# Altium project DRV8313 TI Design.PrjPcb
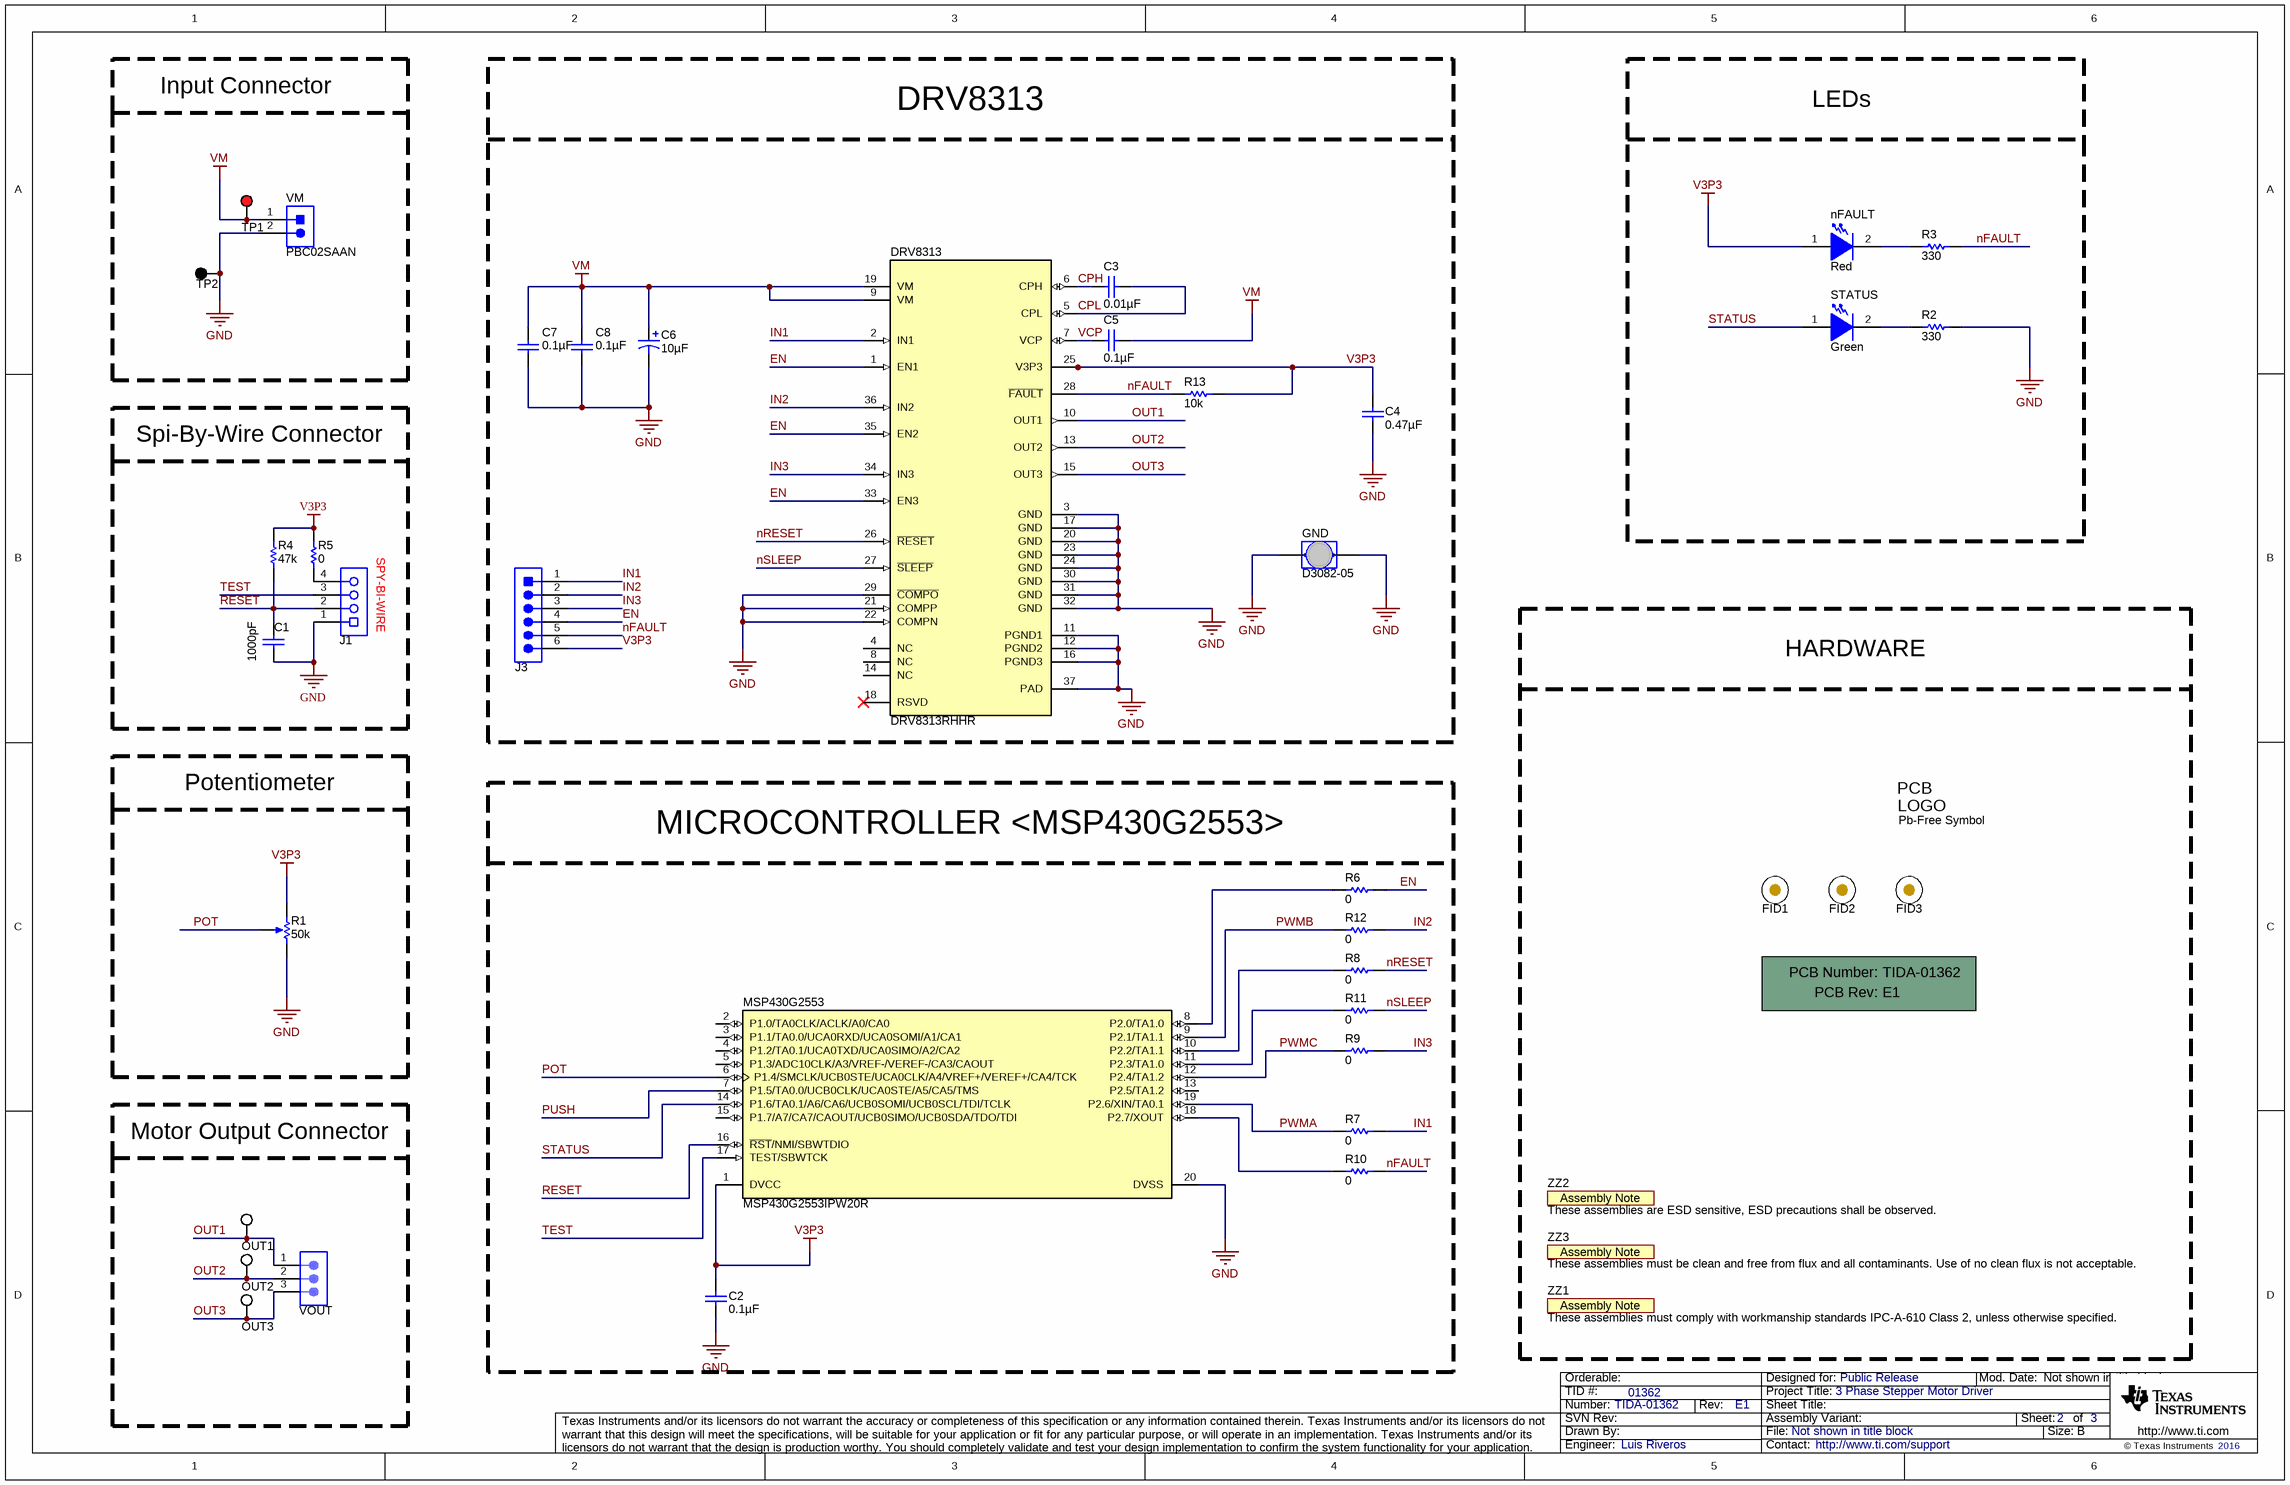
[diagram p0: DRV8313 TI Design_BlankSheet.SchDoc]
CopyrightYear: 2016; PCB_Layout: Luis Riveros; PCB_Rev: E1; PRJ_Customer: Public Release; PRJ_Engineer: Luis Riveros; PRJ_Number: TIDA-01362; PRJ_Title: 3 Phase Stepper Motor Driver; SCH_Rev: E1; TechSupport: http://www.ti.com/support; TID: 01362
1 sheet, 43 parts. Net scope: global (net labels, ports and power ports of the same name join across sheets).
Board file: DRV8313 TI Design_PCB.PcbDoc

## Sheet DRV8313 TI Design_BlankSheet.SchDoc
size 431 x 279 mm; Date: Not shown in title block; ApprovedBy: Not shown in title block; CheckedBy: Not shown in title block; Author: Not shown in title block; CompanyName: Not shown in title block; Engineer: Not shown in title block; Organization: Not shown in title block; Address1: Not shown in title block; Address2: Not shown in title block; Address3: Not shown in title block; Address4: Not shown in title block; DocumentNumber: 1; Revision: Use project parameter SCH_Rev; SheetNumber: 2; SheetTotal: 3; PageSetup: Record=PageOptions¦CenterHorizontal=True¦CenterVertical=True¦PrintScale=1.00¦XCorrection=1.00¦YCorrection=1.00¦PrintKind=0¦BorderSize=5000000¦LeftOffset=0¦BottomOffset=0¦Orientation=2¦PaperLength=1000¦PaperWidth=1000¦Scale=100¦PaperSource=15¦PrintQuality=600¦MediaType=1¦DitherType=10¦PaperKind=Letter¦PrintScaleMode=1

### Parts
!PCB  Printed Circuit Board  (value not drawn)  (mechanical)
C1  ValueDisplayed: 1000pF  [0603L]  (hidden comment: GRM188R71C102KA01D)
C2  ValueDisplayed: 0.1µF  [0603L]  (hidden comment: C0603C104K8RACTU)
C3  0.01µF  [0603]
C4  ValueDisplayed: 0.47µF  [0603]  (hidden comment: GCM188R71C474KA55D)
C5  ValueDisplayed: 0.1µF  [0805_HV]  (hidden comment: C2012X5R2A104K125AA)
C6  ValueDisplayed: 10µF  [SM_RADIAL_D8]  (hidden comment: EEE-FK1K100XP)
C7  ValueDisplayed: 0.1µF  [0805_HV]  (hidden comment: C2012X5R2A104K125AA)
C8  ValueDisplayed: 0.1µF  [0805_HV]  (hidden comment: C2012X5R2A104K125AA)
DRV8313  DRV8313RHHR  [RHH0036C]
FID1  Fiducial  [Fiducial10-20]  (value not drawn)
FID2  Fiducial  [Fiducial10-20]  (value not drawn)
FID3  Fiducial  [Fiducial10-20]  (value not drawn)
GND  D3082-05  [Harwin_D3082-05]
J1  851-43-004-20-001000  [CONN_851-43-004-20-001000]  (value not drawn)
J3  PEC06SAAN  [Sullins_PEC06SAAN]  (value not drawn)
Logo2  Pb-Free Symbol  [Pb-Free_Overlay_Small]  (no BOM)
MSP430G2553  MSP430G2553IPW20R  [PW0020A_N]
nFAULT  value Red  [LED_LTST-C170_Red]  (hidden comment: LTST-C170KRKT)
OUT1  5002  [Keystone5002]  (value not drawn)
OUT2  5002  [Keystone5002]  (value not drawn)
OUT3  5002  [Keystone5002]  (value not drawn)
R1  value 50k  [Bourns_3352T]  (hidden comment: 3352T-1-503LF)
R2  ValueDisplayed: 330  [0603]  (hidden comment: CRCW0603330RJNEA)
R3  ValueDisplayed: 330  [0603]  (hidden comment: CRCW0603330RJNEA)
R4  value 47k  [0603L]  (hidden comment: CRCW060347K0JNEA)
R5  value 0  [0603L]  (hidden comment: CRCW06030000Z0EA)
R6  value 0  [0603L]  (hidden comment: CRCW06030000Z0EA)
R7  ValueDisplayed: 0  [0805_HV]  (hidden comment: ERJ-6GEY0R00V)
R8  value 0  [0603L]  (hidden comment: CRCW06030000Z0EA)
R9  ValueDisplayed: 0  [0805_HV]  (hidden comment: ERJ-6GEY0R00V)
R10  value 0  [0603L]  (hidden comment: CRCW06030000Z0EA)
R11  value 0  [0603L]  (hidden comment: CRCW06030000Z0EA)
R12  ValueDisplayed: 0  [0805_HV]  (hidden comment: ERJ-6GEY0R00V)
R13  ValueDisplayed: 10k  [0805_HV]  (hidden comment: CRCW080510K0JNEA)
STATUS  value Green  [LTST-C170KGKT_Green]  (hidden comment: LTST-C170KGKT)
TP1  5000  [Keystone5000]  (value not drawn)
TP2  5001  [Keystone5001]  (value not drawn)
VM  PBC02SAAN  [Sullins_PBC02SAAN]
VOUT  PBC03SAAN  [PBC03SAAN]  (value not drawn)
ZZ1  These assemblies must comply with workmanship standards IPC-A-610 Class 2, unless otherwise specified.  [AssemblyNote]  (no BOM)
ZZ2  These assemblies are ESD sensitive, ESD precautions shall be observed.  [AssemblyNote]  (no BOM)
ZZ3  These assemblies must be clean and free from flux and all contaminants. Use of no clean flux is not acceptable.  [AssemblyNote]  (no BOM)

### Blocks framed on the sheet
DRV8313: C3-C8 DRV8313 GND J3 R13
SPY-BI-WIRE: C1 J1 R4 R5
HARDWARE: !PCB FID1-FID3 Logo2 ZZ1-ZZ3

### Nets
GND: C1.2 C2.2 C4.2 C6.2(-) C7.1 C8.2 DRV8313.3(GND) DRV8313.11(PGND1) DRV8313.12(PGND2) DRV8313.16(PGND3) DRV8313.17(GND) DRV8313.20(GND) DRV8313.21(COMPP) DRV8313.22(COMPN) DRV8313.23(GND) DRV8313.24(GND) DRV8313.29(~{COMPO}) DRV8313.30(GND) DRV8313.31(GND) DRV8313.32(GND) DRV8313.37(PAD) GND.1 GND.2 J1.1 MSP430G2553.20(DVSS) R1.3(CW) R2.2 TP2.1 VM.2
V3P3: C2.1 C4.1 DRV8313.25(V3P3) J3.6 MSP430G2553.1(DVCC) nFAULT.1(A) R1.1(CCW) R4.2 R5.2 R13.2
VM: C5.2 C6.1(+) C7.2 C8.1 DRV8313.9(VM) DRV8313.19(VM) TP1.1 VM.1
CPH: C3.2 DRV8313.6(CPH)
CPL: C3.1 DRV8313.5(CPL)
EN: DRV8313.1(EN1) DRV8313.33(EN3) DRV8313.35(EN2) J3.4 R6.1
IN1: DRV8313.2(IN1) J3.1 R7.2
IN2: DRV8313.36(IN2) J3.2 R12.2
IN3: DRV8313.34(IN3) J3.3 R9.2
nFAULT: DRV8313.28(~{FAULT}) J3.5 R3.2 R10.1 R13.1
nRESET: DRV8313.26(~{RESET}) R8.1
nSLEEP: DRV8313.27(~{SLEEP}) R11.1
OUT1: DRV8313.10(OUT1) OUT1.1 VOUT.1
OUT2: DRV8313.13(OUT2) OUT2.1 VOUT.2
OUT3: DRV8313.15(OUT3) OUT3.1 VOUT.3
POT: MSP430G2553.6(P1.4/SMCLK/UCB0STE/UCA0CLK/A4/VREF+/VEREF+/CA4/TCK) R1.2(WIPER)
PUSH: MSP430G2553.7(P1.5/TA0.0/UCB0CLK/UCA0STE/A5/CA5/TMS)
PWMA: MSP430G2553.19(P2.6/XIN/TA0.1) R7.1
PWMB: MSP430G2553.9(P2.1/TA1.1) R12.1
PWMC: MSP430G2553.12(P2.4/TA1.2) R9.1
RESET: C1.1 J1.2 MSP430G2553.16(~{RST}/NMI/SBWTDIO) R4.1
STATUS: MSP430G2553.14(P1.6/TA0.1/A6/CA6/UCB0SOMI/UCB0SCL/TDI/TCLK) STATUS.1(A)
TEST: J1.3 MSP430G2553.17(TEST/SBWTCK)
VCP: C5.1 DRV8313.7(VCP)
NetJ1_4: J1.4 R5.1
NetMSP430G2553_8: MSP430G2553.8(P2.0/TA1.0) R6.2
NetMSP430G2553_10: MSP430G2553.10(P2.2/TA1.1) R8.2
NetMSP430G2553_11: MSP430G2553.11(P2.3/TA1.0) R11.2
NetMSP430G2553_18: MSP430G2553.18(P2.7/XOUT) R10.2
NetnFAULT_2: nFAULT.2(K) R3.1
NetR2_1: R2.1 STATUS.2(K)

Not connected (* = marked no-connect by the designer): DRV8313 4(NC) 8(NC) 14(NC) 18(RSVD)*; MSP430G2553 2(P1.0/TA0CLK/ACLK/A0/CA0) 3(P1.1/TA0.0/UCA0RXD/UCA0SOMI/A1/CA1) 4(P1.2/TA0.1/UCA0TXD/UCA0SIMO/A2/CA2) 5(P1.3/ADC10CLK/A3/VREF-/VEREF-/CA3/CAOUT) 13(P2.5/TA1.2) 15(P1.7/A7/CA7/CAOUT/UCB0SIMO/UCB0SDA/TDO/TDI)

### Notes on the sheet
- Input Connector
- LEDs
- Spi-By-Wire Connector
- Potentiometer
- MICROCONTROLLER <MSP430G2553>
- Motor Output Connector

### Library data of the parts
!PCB = PCB: Manufacturer: Any; PartNumber: TIDA-01362; SymbolCreator: a0412235
C1 = GRM188R71C102KA01D: CAP, CERM, 1000 pF, 16 V, +/- 10%, X7R, 0603; Manufacturer: MuRata; Polarized: N; CompType: Capacitor; Value: 1000pF; U/M: EA; Cap_F: 0.000000001; Tolerance_%: 10; Value1: Unknown; VDC_V: 16; Value2: 16V; TaMin_C: -55; TaMax_C: 125; Cap_Case: 0603; AEC Category: Q200
C2 = C0603C104K8RACTU: CAP, CERM, 0.1 µF, 10 V, +/- 10%, X7R, 0603; Manufacturer: Kemet; Polarized: N; CompType: Capacitor; Value: 0.1uF; U/M: EA; Cap_F: 0.0000001; Tolerance_%: 10; Value1: Unknown; Value2: 10V; TaMin_C: -55; TaMax_C: 125; Cap_Case: 0603; AEC Category: Q200
C3 = Cap: Capacitor; Manufacturer: Murata; MFG Part Number: GCM188R72A103KA37D; Value: .01uF; Cap Voltage: 100V
C4 = GCM188R71C474KA55D: CAP, CERM, 0.47 µF, 16 V, +/- 10%, X7R, AEC-Q200 Grade 1, 0603; Manufacturer: MuRata; Polarized: N; CompType: Capacitor; Value: 0.47uF; U/M: EA; Cap_F: 0.00000047; Tolerance_%: 10; Value1: Unknown; VDC_V: 16; Value2: 16V; TaMin_C: -55; TaMax_C: 125; SizeArea_mm2: 1.28; SizeAreaWB_mm2: 4.68; SizeX_mm: 1.6; SizeY_mm: 0.8; SizeZ_mm: 1; AEC Category: Q200; AEC Qualified: Y
C5 C7 C8 = C2012X5R2A104K125AA: CAP, CERM, 0.1 µF, 100 V, +/- 10%, X5R, 0805; Manufacturer: TDK; Polarized: N; CompType: Capacitor; Value: 0.1uF; U/M: EA; Cap_F: 0.0000001; Tolerance_%: 10; ESR_ohm: 0.020726; Value1: 0.020726 ohm; VDC_V: 100; Value2: 100V; IRMS_A: 1.456; TaMin_C: -55; TaMax_C: 85; Cap_Case: 0805; SizeArea_mm2: 2.5; SizeAreaWB_mm2: 6.75; SizeX_mm: 2; SizeY_mm: 1.25; SizeZ_mm: 1.45; AEC Category: Q200
C6 = EEE-FK1K100XP: CAP, AL, 10 µF, 80 V, +/- 20%, 2.4 ohm, AEC-Q200 Grade 2, SMD; Manufacturer: Panasonic; Polarized: Y; CompType: Capacitor; Value: 10uF; U/M: EA; Cap_F: 0.00001; Tolerance_%: 20; Value1: 2.4 ohm; VDC_V: 80; Value2: 80V; ESR_ohm: 2.4; IRMS_A: 0.06; TaMin_C: -55; TaMax_C: 105; Cap_Case: D8; SizeAreaWB_mm2: 84.28; SizeArea_mm2: 51.48; SizeX_mm: 7.8; SizeY_mm: 6.6; SizeZ_mm: 7.7; AEC Category: Q200; AEC Grade: 2
DRV8313 = DRV8313RHHR: 2.5-A Triple 1/2-H Bridge Driver, RHH0036C; Manufacturer: Texas Instruments; SymbolCreator: Altium; SizeArea_mm2: 36; SizeAreaWB_mm2: 64; SizeX_mm: 6; SizeZ_mm: 1; CompType: IC; U/M: EA
FID1-FID3 = Fiducial: Fiducial mark.  There is nothing to buy or mount.; SymbolCreator: codlsc
GND = D3082-05: 1mm Uninsulated Shorting Plug, 10.16mm spacing, TH; Manufacturer: Harwin; SymbolCreator: a0799628; CompType: Jumper Wire
J1 = 851-43-004-20-001000: SOCKET .050" GRID SIP 4 POS R/A, TH; Manufacturer: Mill-Max; SymbolCreator: a0411947; CompType: Header
J3 = PEC06SAAN: Header, 100mil, 6x1, Tin, TH; Manufacturer: Sullins Connector Solutions; SymbolCreator: a0412235; U/M: EA
Logo2 = Pb-Free: SymbolCreator: a0412235
MSP430G2553 = MSP430G2553IPW20R: 16 MHz Mixed Signal Microcontroller with 16 KB Flash, 512 B SRAM and 24 GPIOs, -40 to 85 degC, 20-pin SOP (PW), Green (RoHS & no Sb/Br); Alternate Manufacturer: Texas Instruments; Alternate PartNumber: Equivalent; ADC: 10-bit SAR; ADC Channels: 8; Brown Out Reset: Yes; Flash(KB): 16; GPIO: 24; Pin/Package: 0DIESALE, 0WAFERSALE, 20PDIP, 20TSSOP, 28TSSOP, 32QFN; SRAM(B): 512; SubFamily: Value Line; Timers - 16-bit: 2; USCI_A (UART/LIN/IrDA/SPI): 1
nFAULT = LTST-C170KRKT: LED, Red, SMD; Manufacturer: Lite-On; Vf_V: 2; Value2: 2V; Io_A: 0.02; Value1: W; SizeAreaWB_mm2: 6.75; SizeArea_mm2: 2.5; SizeY_mm: 1.25; SizeZ_mm: 1.2; U/M: EA
OUT1-OUT3 = 5002: Test Point, Miniature, White, TH; Manufacturer: Keystone; CompType: Test Point Loop; ContactFinish: Silver
R1 = 3352T-1-503LF: Trimming Potentiometer, 50K, 0.5W, TH; Manufacturer: Bourns; Sim Note: Enter the Resistance value and the set point into parameter fields.; SymbolCreator: a0412235; CompType: Trimmer
R2 R3 = CRCW0603330RJNEA: RES, 330, 5%, 0.1 W, 0603; Manufacturer: Vishay-Dale; CompType: Resistor; Value: 330; Value_Code: 330R; Tolerance_%: 5; Power_W: 0.1; Value2: 0.1W; VDC_V: 75; TempCo: 200 ppm/C; SizeArea_mm2: 1.28; SizeX_mm: 1.6; SizeY_mm: 0.8; SizeZ_mm: 1; EIA_Code: E24; U/M: EA; AEC Category: Q200
R4 = CRCW060347K0JNEA: RES, 47 k, 5%, 0.1 W, 0603; Manufacturer: Vishay-Dale; CompType: Resistor; Res_ohm: 47000; Value_Code: 47k0; Tolerance_%: 5; Power_W: 0.1; Value2: 0.1W; VDC_V: 75; TempCo: 200 ppm/C; EIA_Code: E24; U/M: EA; AEC Category: Q200
R5 R6 R8 R10 R11 = CRCW06030000Z0EA: RES, 0, 5%, 0.1 W, 0603; Manufacturer: Vishay-Dale; CompType: Resistor; Value_Code: 0000; Tolerance_%: 5; Power_W: 0.1; Value2: 0.1W; VDC_V: 75; TempCo: 200 ppm/C; EIA_Code: E24; U/M: EA; AEC Category: Q200
R7 R9 R12 = ERJ-6GEY0R00V: RES, 0, 5%, 0.125 W, 0805; Manufacturer: Panasonic; CompType: Resistor; Value: 0; Value_Code: 0000; Tolerance_%: 5; Power_W: 0.125; Value2: 0.125W; VDC_V: 150; TempCo: 600 ppm/C; SizeArea_mm2: 2.5; SizeX_mm: 2; SizeY_mm: 1.25; SizeZ_mm: 1.45; EIA_Code: E24; U/M: EA; AEC Category: Q200
R13 = CRCW080510K0JNEA: RES, 10 k, 5%, 0.125 W, 0805; Manufacturer: Vishay-Dale; CompType: Resistor; Value: 10k; Res_ohm: 10000; Value_Code: 10k0; Tolerance_%: 5; Power_W: 0.125; Value2: 0.125W; VDC_V: 150; TempCo: 200 ppm/C; SizeArea_mm2: 2.5; SizeX_mm: 2; SizeY_mm: 1.25; SizeZ_mm: 1.45; EIA_Code: E24; U/M: EA; AEC Category: Q200
STATUS = LTST-C170KGKT: LED, Green, SMD; Manufacturer: Lite-On; Vf_V: 2; Value2: 2V; Io_A: 0.02; Value1: W; U/M: EA
TP1 = 5000: Test Point, Miniature, Red, TH; Manufacturer: Keystone; CompType: Test Point Loop; ContactFinish: Silver
TP2 = 5001: Test Point, Miniature, Black, TH; Manufacturer: Keystone; CompType: Test Point Loop; ContactFinish: Silver
VM = PBC02SAAN: Header, 100mil, 2x1, Gold, TH; Manufacturer: Sullins Connector Solutions; SymbolCreator: a0412235; Pitch_mm: 2.54; Gender: Male; Shrouded: N; Row_Count: 1; Current_A: 3; Voltage_V: 1800; Cert_UL: Y
VOUT = PBC03SAAN: Header, 100mil, 3x1, Gold, TH; Manufacturer: Sullins Connector Solutions
ZZ1-ZZ3 = AssemblyNote: SymbolCreator: codlsc

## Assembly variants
001: not fitted FID1 FID2 FID3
